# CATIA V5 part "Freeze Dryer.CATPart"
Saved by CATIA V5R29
Part number: kazan
Revision: HERHANG?
Definition: B??MEYEN
Nomenclature: kazan
Source: Unknown
Bounding box of the stored display mesh (mm): x -530.254 to 530.254, y -530.254 to 530.254, z -1560 to 0
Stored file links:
  C:\가치같이\SmartFactory_Freeze dryer\Freeze Dryer.CATPart
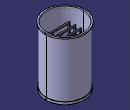
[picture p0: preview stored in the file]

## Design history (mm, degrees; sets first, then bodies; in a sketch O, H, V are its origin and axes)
Set1
  Sketch1 on face of Solid1, origin (0, 0, 0), H (1, 0, 0), V (0, 1, 0)
    arc A1 centre (0, 0) radius 492 from (-416.5715, -261.7865) to (333.4285, -361.7865) ccw
    reference projected arc E1 centre (0, 0) radius 492 from (-492, 0) to (492, 0) ccw from edge [face of Solid1 | face of Solid1]
    reference projected arc E2 centre (0, 0) radius 492 from (-492, 0) to (492, 0) ccw from edge [face of Solid1 | face of Solid1]
    line L1 (-416.5715, -261.7865) -> (333.4285, -261.7865)
    line L2 (333.4285, -261.7865) -> (333.4285, -361.7865)
    length L1 = 750
    length L2 = 100
    concentricity: A1 E1
    coincidence: A1 E2
    horizontal: L1 H
    vertical: L2 V
Body1 "Kes-Ekstr?yon2" (main body)
  Solid1: solid without history
  Pocket1: profile Sketch1, direction (0, 0, -1), up to face of Solid1
  DatumSurface1
  Plane1: type Offset, RefPlane DatumSurface1, Offset 1600
  DatumCurve1
  Sketch2 on Plane1, origin (0, -94.0756, 0), H (-1, 0, 0), V (0, 0, 1)
    line L1 (-202.4469, -920) -> (327.5531, -920)
    line L2 (327.5531, -920) -> (327.5531, -330)
    line L3 (327.5531, -330) -> (-202.4469, -330)
    line L4 (-202.4469, -330) -> (-202.4469, -920)
    line L5 (357.5531, -300) -> (-232.4469, -300)
    line L6 (-232.4469, -300) -> (-232.4469, -1500)
    line L7 (357.5531, -1500) -> (357.5531, -300)
    line L8 (-202.4469, -1500) -> (-202.4469, -950)
    line L9 (-202.4469, -950) -> (327.5531, -950)
    line L10 (327.5531, -950) -> (327.5531, -1500)
    point P11 (-202.4469, -950)
    line L11 (327.5531, -1500) -> (357.5531, -1500)
    line L12 (-202.4469, -1500) -> (-232.4469, -1500)
    reference intersected line E1 (-482.9221, -1500) -> (482.9219, -1500) from face of Solid1
    reference projected line E2 through (-282.4469, 0) direction (0, -1) from edge of DatumCurve1
    length L2 = 590
    length L3 = 530
    distance L2 L7 = 30
    distance L5 L3 = 30
    distance L6 L4 = 30
    distance L9 L1 = 30
    length L10 = 550
    distance L6 E2 = 50
    horizontal: L1 H, L3 H, L5 H, L9 H, L11 H, L12 H
    vertical: L2 V, L4 V, L6 V, L7 V, L8 V, L10 V
    coincidence: P11 L4, L12 L11, L11 E1, L10 L2
  Pad1: profile Sketch2, direction (0, 1, 0), length 30
  RectPattern1: of Pad1, direction 1 instances 4, spacing 150, along edge [face of Pad1 from Sketch2.L6 | face of Pad1 from Sketch2.L5], Nu 2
